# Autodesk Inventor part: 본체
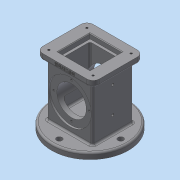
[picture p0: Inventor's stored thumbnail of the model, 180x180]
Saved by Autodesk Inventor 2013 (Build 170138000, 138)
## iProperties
Created: 2018-10
Part Number: 본체
Material: 일반
Document SubType Name: Modeling
Designer: dgall
Density: 1 g/cm^3
Author: dgall
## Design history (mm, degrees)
sketch "스케치1"
  geometry: L1 (0, 0)-(74, 0); L2 (74, 0)-(74, 66); L3 (74, 66)-(0, 66); L4 (0, 66)-(0, 0)
  constraints: 8 end point, 2 parallel, 1 horizontal, 1 perpendicular
  dimensions: "d0" = 74 distance of L2.end L3.end; "d2" = 66 distance of L1.end L2.end
extrude "돌출1" new body sketch "스케치1" distance "d3" = 108; taper "d4" = 0 deg
sketch "스케치2"
  geometry: L1 (0, 0)-(74, 0) reference; L2 (74, 0)-(74, 66) reference; L3 (74, 66)-(0, 66) reference; L4 (0, 66)-(0, 0) reference; L5 (0, 0)-(74, 0) reference; L6 (74, 0)-(74, 66) reference; L7 (74, 66)-(0, 66) reference; L8 (0, 66)-(0, 0) reference; L9 (-9, -8)-(83, -8); L10 (83, -8)-(83, 74); L11 (83, 74)-(-9, 74); L12 (-9, 74)-(-9, -8); 4 further points
  constraints: 8 end point, 4 midpoint, 2 parallel, 1 horizontal, 1 horizontal alignment, 1 perpendicular, 1 vertical alignment
  dimensions: "d5" = 92 distance of L10.end L11.end; "d7" = 82 distance of L9.end L10.end
extrude "돌출2" join sketch "스케치2" distance "d8" = 10; taper "d9" = 0 deg
sketch "스케치4"
  geometry: L1 (0, 0)-(-74, 0) reference; L2 (0, 66)-(0, 0) reference; L3 (-74, 66)-(0, 66) reference; L4 (-74, 0)-(-74, 66) reference; L5 (0, 0)-(-74, 0) reference; L6 (0, 66)-(0, 0) reference; L7 (-74, 66)-(0, 66) reference; L8 (-74, 0)-(-74, 66) reference; L9 (-83, 74)-(-83, -8) reference; C1 r 62.5 at (-37, 33); 2 further points
  constraints: 2 midpoint, 1 centre point, 1 horizontal alignment, 1 vertical alignment
  dimensions: "d14" = 125 diameter of C1
extrude "돌출4" join sketch "스케치4" distance "d16" = 10; taper "d17" = 0 deg
sketch "스케치5"
  geometry: L1 (83, 74)-(-9, 74) reference; L2 (-9, 74)-(-9, -8) reference; L3 (11, 7)-(63, 7); L4 (63, 7)-(63, 59); L5 (63, 59)-(11, 59); L6 (11, 59)-(11, 7); L7 (15, 11)-(59, 11); L8 (59, 11)-(59, 55); L9 (59, 55)-(15, 55); L10 (15, 55)-(15, 11); 8 further points
  constraints: 16 end point, 7 midpoint, 4 parallel, 4 perpendicular, 2 horizontal, 2 horizontal alignment, 2 vertical alignment
  dimensions: "d18" = 52 distance of L4.end L5.end; "d20" = 44 distance of L8.end L9.end
extrude "돌출5" cut sketch "스케치5" distance "d21" = 82; taper "d22" = 0 deg
extrude "돌출6" cut sketch "스케치5" distance "d23" = 8; taper "d24" = 0 deg
sketch "스케치6"
  geometry: C1 r 62.5 at (0, 0) reference; C2 r 28 at (0, 0); 1 further point
  constraints: 1 centre point, 1 coincident
  dimensions: "d25" = 56 diameter of C2
extrude "돌출7" cut sketch "스케치6" distance "d27" = 18; taper "d28" = -10 deg
sketch "스케치7"
  geometry: L1 (0, -88)-(0, 0) reference; L2 (0, -88)-(74, -88) reference; L3 (74, -88)-(74, 0) reference; L4 (74, 0)-(0, 0) reference; L5 (0, -88)-(0, 0) reference; L6 (83, 0)-(-9, 0) reference; C1 r 35 at (37, -44); C2 r 24 at (37, -44); 3 further points
  constraints: 2 centre point, 2 midpoint, 1 coincident, 1 horizontal alignment, 1 vertical alignment
  dimensions: "d29" = 70 diameter of C1; "d31" = 48 diameter of C2
  node "투영된 루프4"
extrude "돌출8" cut sketch "스케치7" stored distance "d32" = 18; taper "d33" = 0 deg
extrude "돌출9" cut sketch "스케치7" distance "d34" = 3; taper "d35" = 0 deg
sketch "스케치8"
  geometry: C1 r 24 at (37, 44) reference; C2 r 35 at (37, 44); 1 further point
  constraints: 1 centre point, 1 coincident
  dimensions: "d36" = 70 diameter of C2
extrude "돌출10" cut sketch "스케치8" distance "d38" = 3; taper "d39" = 0 deg
fillet "모깎기1" dims "d40" = 3
fillet "모깎기2" dims "d41" = 10
fillet "모깎기3" dims "d42" = 3
sketch "스케치9"
  geometry: A1 r 10 centre (1, 64) between (1, 74) and (-9, 64) reference; 2 further points
  constraints: 1 coincident
hole "구멍1" sketch "스케치9" at (1, 64) diameter "d43" = 3.242; stored, may be unused: countersink angle "d47" = 90 deg, drill point angle "d49" = 118 deg; dims "d44" = 4, "d45" = 4, "d46" = 2, "d48" = 6
node "작업 평면1"
node "작업 평면2"
chamfer "모따기1" distance "d50" = 1; stored, may be unused: second distance "d51" = 2, angle "d52" = 45 deg
sketch "스케치10"
  geometry: C1 r 24 at (0, 0) reference; 2 further points
  constraints: 1 vertical alignment
  dimensions: "d53" = 29 distance of C1.centre point (0, -29)
hole "구멍2" sketch "스케치10" at (0, -29) diameter "d54" = 3.242; stored, may be unused: countersink angle "d58" = 90 deg, drill point angle "d60" = 118 deg; dims "d55" = 4, "d56" = 4, "d57" = 2, "d59" = 6
sketch "스케치11"
  geometry: L1 (95, 92.5)-(95, -32.5) reference; L2 (88, 92.5)-(88, -32.5) reference; L3 (-13, -1)-(-13, 61) reference; 5 further points
  constraints: 2 horizontal alignment, 2 midpoint
  dimensions: "d65" = 43 distance of point (58, 30) point (15, 30); "d67" = 37 distance from line of L1 point (58, 30)
hole "구멍3" sketch "스케치11" at (15, 30), (58, 30) diameter "d68" = 4.134; stored, may be unused: countersink angle "d72" = 90 deg, drill point angle "d74" = 118 deg; dims "d69" = 4, "d70" = 4, "d71" = 2, "d73" = 30
sketch "스케치12"
  geometry: C1 r 59.5 at (0, 0) reference; C2 r 4.5 at (0, 50); C3 r 4.5 at (-50, 0); C4 r 4.5 at (0, -50); C5 r 4.5 at (50, 0); A1 r 50 centre (0, 0) between (0, 50) and (-50, 0); 1 further point
  constraints: 5 centre point, 4 point on circle, 3 equal radius, 2 horizontal alignment, 2 vertical alignment, 1 coincident
  dimensions: "d75" = 9 diameter of C2; "d77" = 100 diameter of A1
extrude "돌출11" cut sketch "스케치12" stored distance "d78" = 3; taper "d79" = 0 deg
node "작업 평면3"
sketch "스케치14"
  geometry: L1 (82, 0)-(72, 0) reference; L2 (72, 0)-(72, -7) reference; L3 (82, -7)-(72, -7) reference; L4 (82, -7)-(82, 0) reference; L5 (-10, 0)-(-10, -7) reference; 2 further points
  constraints: 1 other
  dimensions: "d81" = 46 distance from line of L5 point (36, -4); "d82" = 4 distance from line of point (36, -4) L1
feature "엠보싱1" sketch "스케치14" dims "d0" = 74, "d2" = 66, "d5" = 92, "d7" = 82, "d83" = 0.5, "d84" = 0
node "솔리드1"
mirror "대칭1"
mirror "대칭2"
pattern_circular "원형 패턴1" dims angle "d62" = 360 deg
mirror "대칭3"
node "투영된 루프1"
node "투영된 루프3"
node "투영된 루프5"
node "투영된 루프6"
